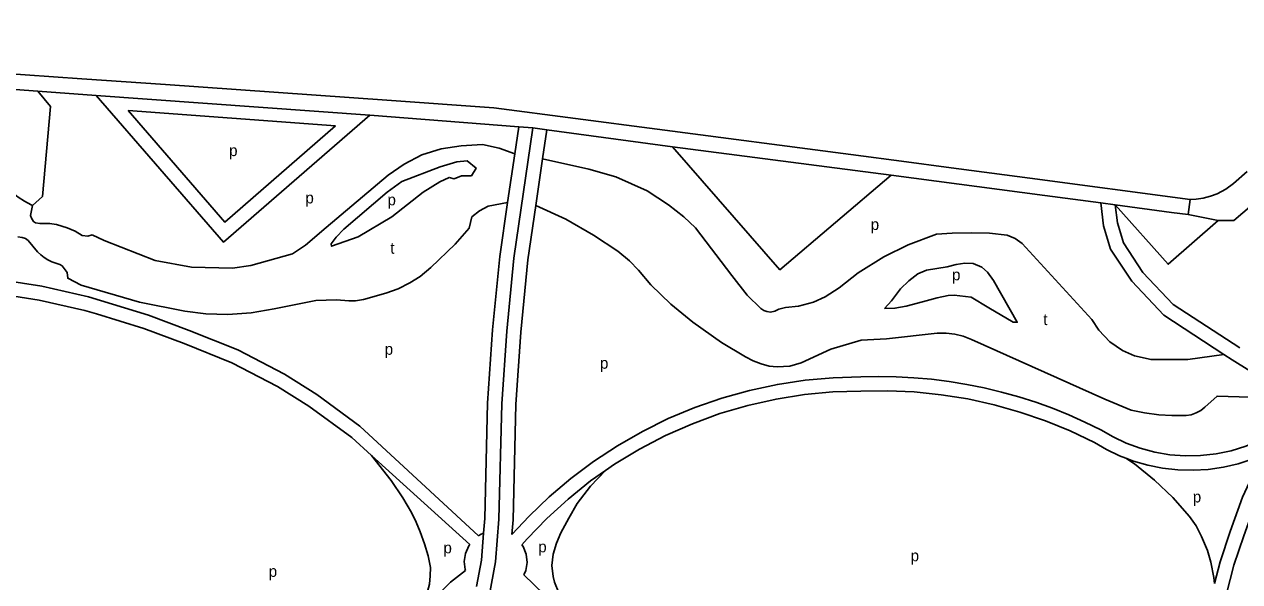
# Model space of a CAD drawing. Extents: x 155696 to 157795, y 382328 to 384028.
# Drawn here: x 155982.6 to 156412.1, y 383804.3 to 384001.4 of the extents above; entities that cross this region are included whole.
import ezdxf

# ---------------------------------------------------------------- set-up
doc = ezdxf.new("R2010")
doc.units = 0
for name, color, linetype in [('BLT_Basislijn', 7, 'Continuous'), ('BLT_Centroide', 7, 'Continuous'), ('BLT_Vlakafsluiter', 7, 'Continuous')]:
    doc.layers.add(name, color=color, linetype=linetype)

msp = doc.modelspace()

# ---------------------------------------------------------------- linework, layer by layer
at = {"layer": 'BLT_Basislijn'}
for p, q in [((155919.44, 383988.02), (156002.92, 383982.15)), ((156002.92, 383982.15), (156032.52, 383980.07)), ((155987.33, 383977.76), (155972.88, 383978.81)), ((156008.03, 383976.25), (155987.33, 383977.76)), ((156008.03, 383976.25), (156104.67, 383969.31)), ((156110.7, 383974.55), (156032.52, 383980.07)), ((156148.5, 383971.88), (156110.7, 383974.55)), ((156148.5, 383971.88), (156206.23, 383964.32)), ((156019.28, 383970.91), (156092.63, 383965.48)), ((156104.67, 383969.31), (156157.33, 383965.2)), ((156167.26, 383964.04), (156211.67, 383958.1)), ((156206.23, 383964.32), (156274.68, 383955.36)), ((156211.67, 383958.1), (156288.91, 383948.09)), ((156274.68, 383955.36), (156294.38, 383952.75)), ((156294.38, 383952.75), (156308.44, 383950.89)), ((156308.44, 383950.89), (156337.97, 383946.96)), ((156337.97, 383946.96), (156394.63, 383939.48)), ((156409.95, 383945.11), (156414.79, 383949.31)), ((156388.03, 383934.92), (156368.17, 383937.56)), ((156394.63, 383939.48), (156393.96, 383934.13)), ((156388.03, 383934.92), (156393.96, 383934.13)), ((156406.48, 383884.71), (156409.5, 383882.74)), ((156409.5, 383882.74), (156426.16, 383872.36)), ((156101.23, 383859.34), (156143.13, 383820.52)), ((156098.31, 383855.28), (156105.26, 383848.99)), ((156105.26, 383848.99), (156140.06, 383817.51)), ((156405.18, 383811.41), (156403.19, 383803.65)), ((156410.02, 383810.17), (156403.26, 383783.78))]:
    msp.add_line(p, q, dxfattribs=at)
for points in [[(156528.08, 384000.1), (156504.25, 384001.4), (156492.87, 383997.5), (156477.56, 383989.59), (156410.02, 383932.03), (156404.54, 383932.08)], [(155985.43, 383937.3), (155989.06, 383940.52), (155991.9, 383972.37), (155987.33, 383977.76)], [(156008.03, 383976.25), (156052.96, 383924.39), (156104.67, 383969.31)], [(155985.43, 383937.3), (155985.05, 383937.52), (155982.66, 383938.82), (155980.38, 383940.32), (155978.6, 383941.71), (155964.9, 383956.68), (155953.95, 383969.98)], [(156019.28, 383970.91), (156053.46, 383931.45), (156092.63, 383965.48)], [(156146.06, 383794.75), (156149.18, 383811.32), (156150.34, 383826.46), (156151.32, 383867.27), (156153.1, 383892.93), (156155.59, 383918.67), (156162.31, 383964.76)], [(156155.93, 383955.62), (156157.33, 383965.2)], [(156165.78, 383953.89), (156167.26, 383964.04)], [(156155.93, 383955.62), (156150.47, 383957.58), (156144.51, 383958.9), (156137, 383958.45), (156129.95, 383957.41)], [(156077.36, 383920.2), (156082.02, 383923.28), (156089.25, 383929.54), (156111.24, 383948.06), (156116.79, 383951.95), (156123.09, 383955.3), (156129.95, 383957.41)], [(156153.42, 383938.43), (156155.93, 383955.62)], [(156211.67, 383958.1), (156249.66, 383914.64), (156288.91, 383948.09)], [(156163.38, 383937.39), (156165.78, 383953.89)], [(156165.78, 383953.89), (156182.06, 383950.23), (156191.67, 383947.46), (156202.67, 383942.5), (156210.3, 383937.63), (156215.65, 383933.37), (156219.83, 383929.46), (156232.66, 383912.58), (156238.11, 383905.63), (156242.94, 383900.98), (156243.91, 383900.27), (156245.07, 383899.85), (156246.33, 383899.68), (156247.87, 383899.95), (156249.2, 383900.67), (156251.56, 383901.24), (156256.24, 383901.71), (156261.5, 383903.21), (156265.58, 383905.01), (156270.55, 383908.24), (156277.28, 383913.54), (156286.41, 383919.21), (156294.99, 383923.42), (156304.93, 383927.17), (156310.46, 383927.6), (156317.35, 383927.69), (156323.77, 383927.5), (156329.98, 383926.88), (156332.84, 383925.66), (156335.25, 383923.85), (156359.92, 383897.05), (156362.33, 383893.3), (156366.19, 383889.19), (156370.77, 383886.02), (156375.01, 383884.24), (156380.83, 383882.86), (156386.34, 383882.94), (156393.81, 383882.91), (156406.48, 383884.71)], [(156288.91, 383948.09), (156343.31, 383940.86), (156363.05, 383938.24)], [(156409.95, 383945.11), (156407.28, 383943.17), (156404.18, 383941.5), (156401.79, 383940.62), (156399.17, 383939.91), (156396.78, 383939.59), (156394.63, 383939.48)], [(156153.42, 383938.43), (156146.56, 383937.16), (156143.5, 383935.51), (156140.76, 383933.29), (156139.85, 383929.37), (156134.9, 383923.65), (156126.28, 383915.42), (156122.52, 383912.29), (156118.85, 383909.96), (156114.69, 383907.91), (156110.33, 383906.36), (156102.44, 383904.16), (156099.65, 383903.64), (156097.27, 383903.63), (156092.94, 383903.94), (156085.57, 383903.74), (156070.86, 383900.81), (156062.78, 383899.41), (156054.51, 383898.79), (156046.79, 383899.03), (156039.29, 383899.98), (156023.25, 383903.19), (156002.67, 383909.15), (155997.96, 383911.59), (155997.7, 383913.68)], [(156144.94, 383821.46), (156145.34, 383826.71), (156146.32, 383867.5), (156148.12, 383893.34), (156150.63, 383919.28), (156153.42, 383938.43)], [(156154.93, 383820.98), (156155.33, 383826.21), (156156.31, 383867.03), (156158.08, 383892.51), (156160.56, 383918.07), (156163.38, 383937.39)], [(156163.38, 383937.39), (156173.94, 383932.51), (156183.78, 383926.9), (156192.3, 383921.21), (156196.45, 383917.73), (156199.62, 383914.52), (156204.04, 383909.27), (156211.12, 383902.42), (156218.86, 383896.12), (156229.05, 383888.89), (156237.5, 383883.86), (156240.15, 383882.4), (156243.07, 383881.33), (156245.89, 383880.57), (156248.71, 383880.25), (156253.14, 383880.54), (156257.2, 383881.7), (156267.61, 383886.55), (156278.36, 383889.73), (156287.35, 383890.16), (156305.22, 383892.15), (156308.36, 383892.21), (156311.49, 383891.8), (156314.45, 383891.12), (156317.38, 383889.99), (156364.44, 383868.9), (156373.77, 383865), (156378.53, 383864.01), (156383.54, 383863.37), (156388.15, 383863.09), (156393.18, 383863.06), (156395.01, 383863.36), (156396.8, 383863.99), (156398.35, 383864.85), (156399.82, 383866.05), (156404.14, 383869.98), (156415.84, 383869.63)], [(156363.05, 383938.24), (156363.99, 383930.2), (156366.49, 383921.94), (156373.97, 383910.57), (156385.35, 383898.51), (156406.48, 383884.71)], [(156368.17, 383937.56), (156386.81, 383916.54), (156404.54, 383932.08)], [(156368.17, 383937.56), (156368.9, 383931.22), (156371.06, 383924.08), (156377.9, 383913.69), (156388.58, 383902.37), (156412.14, 383886.98)], [(155984.82, 383933.83), (155985.43, 383937.3)], [(156006.59, 383926.93), (156005.04, 383926.55), (156003.02, 383926.73), (156000.53, 383928.27), (155997.76, 383929.4), (155994.01, 383930.61), (155992.29, 383930.87), (155991.61, 383930.98), (155988.11, 383930.96), (155986.5, 383931.17), (155985.8, 383931.66), (155985.1, 383932.85), (155984.82, 383933.83)], [(156404.54, 383932.08), (156393.96, 383934.13)], [(155997.7, 383913.68), (155995.92, 383916.02), (155995.11, 383916.52), (155992.32, 383917.44), (155990.85, 383918.15), (155989.6, 383918.97), (155988.46, 383919.85), (155987.31, 383920.94), (155983.94, 383924.92), (155982.98, 383925.68), (155981.83, 383926.02), (155980.36, 383926.23)], [(156006.59, 383926.93), (156010.82, 383925.01), (156028.88, 383917.91)], [(156028.88, 383917.91), (156041.74, 383915.48), (156056.2, 383915.22), (156062.62, 383916.07), (156077.36, 383920.2)], [(155904.78, 383910.85), (155906.01, 383911.4), (155914.13, 383912.74), (155926.06, 383913.52), (155941.72, 383914), (155958.65, 383912.92), (155975.07, 383910.94), (155988.73, 383908.79), (156005.29, 383905.09), (156009.55, 383903.77), (156026.45, 383898.58), (156040.89, 383893.2), (156058.05, 383886.28), (156074.5, 383877.67), (156085.98, 383870.54), (156101.23, 383859.34)], [(155896.25, 383900.82), (155899.87, 383903.21), (155907.46, 383906.57), (155914.71, 383907.77), (155926.3, 383908.52), (155941.64, 383908.99), (155958.19, 383907.94), (155974.38, 383905.99), (155987.79, 383903.87), (156004, 383900.26), (156008.07, 383899), (156024.84, 383893.85), (156039.08, 383888.54), (156055.95, 383881.74), (156072.02, 383873.33), (156083.17, 383866.39), (156098.31, 383855.28)], [(156154.93, 383820.98), (156160.97, 383827.51), (156168.1, 383834.36), (156175.71, 383840.83), (156183.77, 383846.86), (156192.22, 383852.42), (156201.04, 383857.47), (156210.16, 383861.98), (156219.55, 383865.9), (156229.15, 383869.24), (156238.9, 383871.96), (156248.74, 383874.07), (156258.61, 383875.57), (156268.46, 383876.45), (156278.24, 383876.74)], [(156278.24, 383876.74), (156284.46, 383876.87), (156290.7, 383876.77), (156296.95, 383876.44), (156303.2, 383875.89), (156309.45, 383875.1), (156315.66, 383874.08), (156321.84, 383872.84), (156327.97, 383871.37), (156334.04, 383869.68), (156340.03, 383867.77), (156345.94, 383865.65), (156351.75, 383863.31), (156357.46, 383860.78), (156363.04, 383858.06)], [(156188.01, 383843.63), (156191.19, 383845.86), (156200.04, 383851.22), (156209.23, 383856.02), (156218.71, 383860.2), (156228.43, 383863.75), (156238.31, 383866.66), (156248.29, 383868.9), (156258.32, 383870.49), (156268.32, 383871.43), (156278.24, 383871.74)], [(156278.24, 383871.74), (156287.66, 383871.84), (156297.12, 383871.41), (156306.58, 383870.44), (156316, 383868.93), (156325.31, 383866.88), (156334.49, 383864.3), (156343.49, 383861.22), (156352.26, 383857.64), (156360.77, 383853.6)], [(156363.04, 383858.06), (156367.37, 383855.52), (156372.01, 383853.33), (156376.93, 383851.51), (156382.09, 383850.13), (156387.42, 383849.22), (156392.85, 383848.81), (156398.33, 383848.91), (156403.78, 383849.52), (156409.12, 383850.64), (156414.28, 383852.24), (156419.21, 383854.28), (156423.86, 383856.72), (156428.17, 383859.5), (156431.39, 383862)], [(156360.77, 383853.6), (156365.1, 383851.07), (156369.71, 383848.85), (156371.94, 383848)], [(156410.02, 383810.17), (156413.56, 383820.52), (156417.81, 383832.33), (156423.21, 383843.96), (156429.03, 383853.67)], [(156120.61, 383791.37), (156123.18, 383795.89), (156124.72, 383799.57), (156125.84, 383803.47), (156126.09, 383806.45), (156126.12, 383809.41), (156125.29, 383813.44), (156124.04, 383817.73), (156122.51, 383822), (156121.1, 383825.36), (156119.45, 383828.85), (156116.32, 383834.01), (156112.23, 383840.11), (156105.26, 383848.99)], [(156371.94, 383848), (156374.58, 383846.99), (156379.65, 383845.52), (156384.89, 383844.47), (156390.24, 383843.87), (156395.64, 383843.73), (156401.04, 383844.05), (156406.36, 383844.84), (156411.57, 383846.06), (156416.59, 383847.71), (156420.67, 383849.43)], [(156371.94, 383848), (156374.95, 383845.96), (156382.01, 383840.28), (156388.48, 383834.11), (156394.43, 383827.44), (156396.8, 383824.03), (156398.68, 383820.32), (156400.71, 383815.4), (156401.96, 383811.22), (156403.01, 383805.8), (156403.19, 383803.65)], [(156405.18, 383811.41), (156408.81, 383822.1), (156413.18, 383834.23), (156418.79, 383846.3), (156420.67, 383849.43)], [(156158.42, 383817.32), (156160.28, 383819.49), (156167.26, 383826.72), (156174.76, 383833.55), (156182.75, 383839.95), (156188.01, 383843.63)], [(156177.52, 383789.11), (156174.06, 383794.96), (156171.45, 383800.39), (156170.01, 383804.18), (156169.46, 383806.14), (156168.99, 383810.1), (156169.54, 383814.12), (156170.71, 383817.95), (156172.24, 383821.63), (156174.99, 383826.8), (156178.03, 383831.94), (156182.65, 383838.07), (156188.01, 383843.63)], [(156142.46, 383802.62), (156144.22, 383811.97), (156144.94, 383821.46)], [(156144.94, 383821.46), (156143.78, 383821), (156143.13, 383820.52)], [(156140.06, 383817.51), (156139.66, 383817), (156138.51, 383814.34), (156138.09, 383811.48), (156138.43, 383808.6), (156138.57, 383808.24)], [(156159.19, 383806.75), (156159.85, 383808.29), (156160.27, 383811.16), (156159.93, 383814.03), (156158.86, 383816.72), (156158.42, 383817.32)], [(156138.57, 383808.24), (156133.2, 383804.11), (156125.01, 383796.03), (156120.61, 383791.37)], [(156159.19, 383806.75), (156173.66, 383792.7), (156177.52, 383789.11)]]:
    msp.add_lwpolyline(points, dxfattribs=at)
for points in [[(156116.04, 383945.79), (156129.54, 383950.98), (156135.41, 383952.78), (156139.09, 383953.11), (156142.25, 383950.58), (156140.6, 383947.86), (156137.06, 383947.87), (156134.55, 383946.74), (156132.71, 383947.26), (156129.4, 383945.71), (156123.56, 383942.05), (156112.48, 383933.38), (156100.57, 383926.22), (156091.22, 383922.92), (156091.01, 383923.84), (156092.82, 383926.12), (156095.48, 383928.96), (156110.78, 383942.03)], [(156286.59, 383900.89), (156289.1, 383903.62), (156292.21, 383907.9), (156295.15, 383910.73), (156298.38, 383913.12), (156301.44, 383914.46), (156308.77, 383915.62), (156311.89, 383916.46), (156314.94, 383916.96), (156317.94, 383916.79), (156320.95, 383915.57), (156323, 383913.73), (156325.11, 383910.84), (156333.51, 383896.06), (156332.06, 383896.11), (156323.45, 383901.17), (156317.22, 383904.95), (156311.27, 383905.62), (156309.16, 383905.56), (156305.27, 383904.73), (156299.99, 383903.23), (156294.21, 383901.78), (156290.26, 383901.01)]]:
    msp.add_lwpolyline(points, close=True, dxfattribs=at)
at = {"layer": 'BLT_Vlakafsluiter'}
for p, q in [((156157.33, 383965.2), (156162.31, 383964.76)), ((156162.31, 383964.76), (156167.26, 383964.04))]:
    msp.add_line(p, q, dxfattribs=at)
msp.add_lwpolyline([(156363.05, 383938.24), (156368.17, 383937.56)], dxfattribs=at)

# ---------------------------------------------------------------- texts
at = {"layer": 'BLT_Centroide'}
for s, p in [('p', (156054.98, 383954.81)), ('p', (156081.94, 383938.08)), ('p', (156110.95, 383937.4)), ('p', (156281.74, 383928.68)), ('t', (156111.94, 383920.28)), ('p', (156310.47, 383910.89)), ('t', (156342.73, 383895.06)), ('p', (156109.97, 383884.57)), ('p', (156186.03, 383879.63)), ('p', (156395.57, 383832.36)), ('p', (156130.73, 383814.36)), ('p', (156164.22, 383814.72)), ('p', (156295.85, 383811.56)), ('p', (156068.97, 383806.04))]:
    msp.add_text(s, height=4, dxfattribs=at).set_placement(p)

doc.saveas('drawing.dxf')
